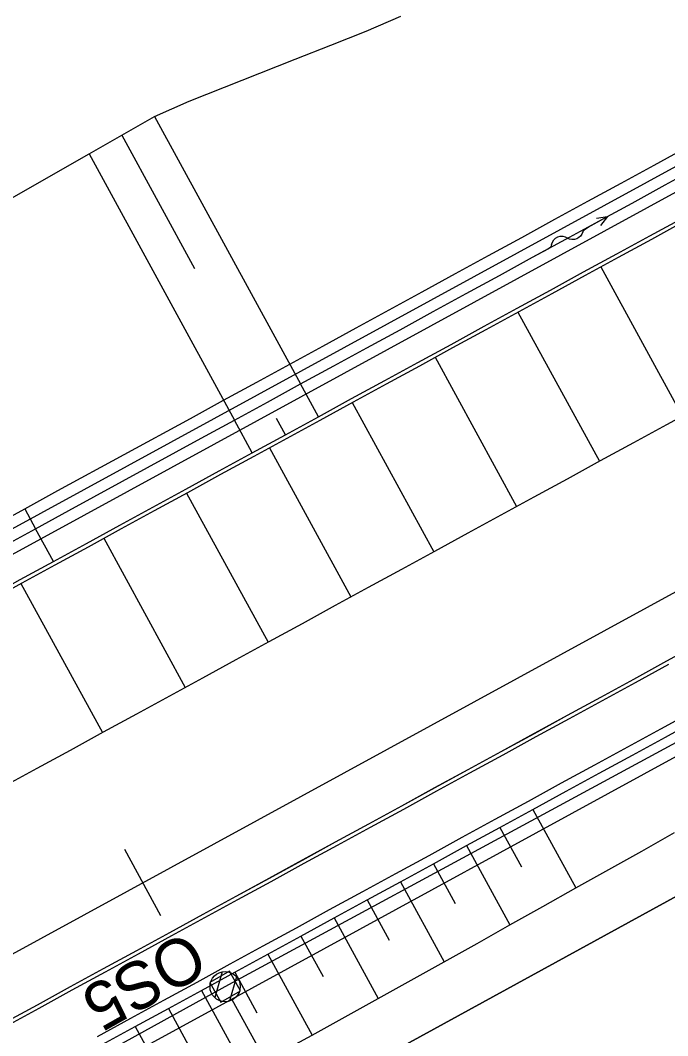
# Model space of a CAD drawing. Extents: x -783978 to -783565, y -1064821 to -1064596.
# Drawn here: x -783827.85 to -783810.7, y -1064718.73 to -1064691.83 of the extents above; entities that cross this region are included whole.
import ezdxf

# ---------------------------------------------------------------- set-up
doc = ezdxf.new("R2010")
doc.units = 0
for name, color, linetype in [('PS 01_01_10', 7, 'Continuous'), ('PS 01_02_501', 7, 'Continuous'), ('PS 01_02_502', 7, 'Continuous'), ('SO 01_50_01', 7, 'Continuous'), ('SO 01_79_02', 7, 'Continuous'), ('SO 01_86_02', 7, 'Continuous'), ('SO 01_86_03', 7, 'Continuous')]:
    doc.layers.add(name, color=color, linetype=linetype)

# ---------------------------------------------------------------- blocks, each defined once
blk = doc.blocks.new('SIPKP')
at = {"layer": 'SO 01_50_01'}
for p, q in [((0, 0), (19.5, 0)), ((67.1, 0.2), (74.2, 0.2)), ((74.2, 0.2), (90.5, 0.2)), ((90.5, 0.2), (79.4, 4.9)), ((79.4, -4.1), (90.5, 0.2))]:
    blk.add_line(p, q, dxfattribs=at)
for centre, radius, start, end in [((19.6, -5.8), 5.82, 37.3192, 90.4169), ((51.6, -5.8), 11.1, 42.7386, 149.222), ((66.6, 17.1), 16.9, 245.3105, 271.7078), ((32.5, 4.2), 10.5, 218.0257, 335.7054)]:
    blk.add_arc(centre, radius, start, end, dxfattribs=at)

msp = doc.modelspace()

# ---------------------------------------------------------------- linework, layer by layer
at = {"layer": 'PS 01_01_10'}
msp.add_lwpolyline([(-783718.942, -1064658.936), (-783725.964, -1064662.689), (-783732.354, -1064665.912), (-783735.21, -1064660.697), (-783789.362, -1064690.348), (-783783.825, -1064700.441), (-783871.436, -1064748.425), (-783875.857, -1064749.835)], dxfattribs=at)
at = {"layer": 'PS 01_02_501'}
msp.add_lwpolyline([(-783952.311, -1064789.972), (-783925.027, -1064771.233), (-783922.857, -1064767.935), (-783921.132, -1064767.225), (-783922.344, -1064769.056), (-783920.816, -1064771.043), (-783917.67, -1064770.417), (-783911.05, -1064766.471), (-783887.429, -1064753.525), (-783871.436, -1064748.425), (-783783.828, -1064700.439), (-783789.362, -1064690.348), (-783735.226, -1064660.707), (-783727.19, -1064659.072), (-783724.297, -1064658.484), (-783715.521, -1064653.988), (-783697.391, -1064644.148), (-783676.268, -1064633.506), (-783655.138, -1064621.894)], dxfattribs=at)
at = {"layer": 'PS 01_02_502'}
msp.add_lwpolyline([(-783952.311, -1064789.972), (-783925.027, -1064771.233), (-783922.857, -1064767.935), (-783921.132, -1064767.225), (-783922.344, -1064769.056), (-783920.816, -1064771.043), (-783917.67, -1064770.417), (-783911.05, -1064766.471), (-783887.429, -1064753.525), (-783871.436, -1064748.425), (-783783.828, -1064700.439), (-783789.362, -1064690.348), (-783735.226, -1064660.707), (-783727.19, -1064659.072), (-783724.297, -1064658.484), (-783715.521, -1064653.988), (-783697.391, -1064644.148), (-783676.268, -1064633.506), (-783655.138, -1064621.894)], dxfattribs=at)
at = {"layer": 'SO 01_50_01'}
for p, q in [((-783868.841, -1064727.56), (-783794.223, -1064686.815)), ((-783868.554, -1064728.087), (-783793.967, -1064687.359)), ((-783818.692, -1064692.119), (-783817.768, -1064691.724)), ((-783819.629, -1064692.489), (-783818.692, -1064692.119)), ((-783820.566, -1064692.86), (-783819.629, -1064692.489)), ((-783821.503, -1064693.231), (-783820.566, -1064692.86)), ((-783822.44, -1064693.601), (-783821.503, -1064693.231)), ((-783867.163, -1064737.91), (-783786.213, -1064693.707)), ((-783823.377, -1064693.972), (-783822.44, -1064693.601)), ((-783824.295, -1064694.378), (-783823.377, -1064693.972)), ((-783825.162, -1064694.876), (-783824.295, -1064694.378)), ((-783824.295, -1064694.378), (-783820.425, -1064701.464)), ((-783826.03, -1064695.373), (-783825.162, -1064694.876)), ((-783825.162, -1064694.876), (-783823.233, -1064698.41)), ((-783811.058, -1064695.666), (-783810.181, -1064695.187)), ((-783849.497, -1064708.734), (-783826.03, -1064695.373)), ((-783826.03, -1064695.373), (-783822.181, -1064702.423)), ((-783811.936, -1064696.145), (-783811.058, -1064695.666)), ((-783810.771, -1064696.193), (-783809.893, -1064695.713)), ((-783812.814, -1064696.625), (-783811.936, -1064696.145)), ((-783811.648, -1064696.672), (-783810.771, -1064696.193)), ((-783813.691, -1064697.104), (-783812.814, -1064696.625)), ((-783812.526, -1064697.151), (-783811.648, -1064696.672)), ((-783811.175, -1064697.539), (-783810.297, -1064697.06)), ((-783811.175, -1064697.539), (-783810.297, -1064697.06)), ((-783811.175, -1064697.539), (-783810.297, -1064697.06)), ((-783814.569, -1064697.583), (-783813.691, -1064697.104)), ((-783813.404, -1064697.63), (-783812.526, -1064697.151)), ((-783811.127, -1064697.627), (-783810.249, -1064697.148)), ((-783815.447, -1064698.062), (-783814.569, -1064697.583)), ((-783814.281, -1064698.11), (-783813.404, -1064697.63)), ((-783812.053, -1064698.018), (-783811.175, -1064697.539)), ((-783812.053, -1064698.018), (-783811.175, -1064697.539)), ((-783812.053, -1064698.018), (-783811.175, -1064697.539)), ((-783812.005, -1064698.106), (-783811.127, -1064697.627)), ((-783816.324, -1064698.542), (-783815.447, -1064698.062)), ((-783815.159, -1064698.589), (-783814.281, -1064698.11)), ((-783812.93, -1064698.498), (-783812.053, -1064698.018)), ((-783812.93, -1064698.498), (-783812.053, -1064698.018)), ((-783812.93, -1064698.498), (-783812.053, -1064698.018)), ((-783812.882, -1064698.585), (-783812.005, -1064698.106)), ((-783817.202, -1064699.021), (-783816.324, -1064698.542)), ((-783816.037, -1064699.068), (-783815.159, -1064698.589)), ((-783813.808, -1064698.977), (-783812.93, -1064698.498)), ((-783813.808, -1064698.977), (-783812.93, -1064698.498)), ((-783813.808, -1064698.977), (-783812.93, -1064698.498)), ((-783813.76, -1064699.065), (-783812.882, -1064698.585)), ((-783814.686, -1064699.456), (-783813.808, -1064698.977)), ((-783814.686, -1064699.456), (-783813.808, -1064698.977)), ((-783814.686, -1064699.456), (-783813.808, -1064698.977)), ((-783818.08, -1064699.5), (-783817.202, -1064699.021)), ((-783816.914, -1064699.547), (-783816.037, -1064699.068)), ((-783814.638, -1064699.544), (-783813.76, -1064699.065)), ((-783818.957, -1064699.979), (-783818.08, -1064699.5)), ((-783815.563, -1064699.935), (-783814.686, -1064699.456)), ((-783815.563, -1064699.935), (-783814.686, -1064699.456)), ((-783815.563, -1064699.935), (-783814.686, -1064699.456)), ((-783817.792, -1064700.027), (-783816.914, -1064699.547)), ((-783815.515, -1064700.023), (-783814.638, -1064699.544)), ((-783819.835, -1064700.459), (-783818.957, -1064699.979)), ((-783818.67, -1064700.506), (-783817.792, -1064700.027)), ((-783816.441, -1064700.415), (-783815.563, -1064699.935)), ((-783816.441, -1064700.415), (-783815.563, -1064699.935)), ((-783816.441, -1064700.415), (-783815.563, -1064699.935)), ((-783816.393, -1064700.502), (-783815.515, -1064700.023)), ((-783820.713, -1064700.938), (-783819.835, -1064700.459)), ((-783819.548, -1064700.985), (-783818.67, -1064700.506)), ((-783817.319, -1064700.894), (-783816.441, -1064700.415)), ((-783817.319, -1064700.894), (-783816.441, -1064700.415)), ((-783817.319, -1064700.894), (-783816.441, -1064700.415)), ((-783817.271, -1064700.982), (-783816.393, -1064700.502)), ((-783821.59, -1064701.417), (-783820.713, -1064700.938)), ((-783820.425, -1064701.464), (-783819.548, -1064700.985)), ((-783818.196, -1064701.373), (-783817.319, -1064700.894)), ((-783818.196, -1064701.373), (-783817.319, -1064700.894)), ((-783818.196, -1064701.373), (-783817.319, -1064700.894)), ((-783818.148, -1064701.461), (-783817.271, -1064700.982)), ((-783819.074, -1064701.852), (-783818.196, -1064701.373)), ((-783819.074, -1064701.852), (-783818.196, -1064701.373)), ((-783819.074, -1064701.852), (-783818.196, -1064701.373)), ((-783822.468, -1064701.896), (-783821.59, -1064701.417)), ((-783821.303, -1064701.944), (-783820.425, -1064701.464)), ((-783819.952, -1064702.332), (-783820.425, -1064701.464)), ((-783819.026, -1064701.94), (-783818.148, -1064701.461)), ((-783823.346, -1064702.376), (-783822.468, -1064701.896)), ((-783819.952, -1064702.332), (-783819.074, -1064701.852)), ((-783819.952, -1064702.332), (-783819.074, -1064701.852)), ((-783819.952, -1064702.332), (-783819.074, -1064701.852)), ((-783822.181, -1064702.423), (-783821.303, -1064701.944)), ((-783819.904, -1064702.419), (-783819.026, -1064701.94)), ((-783810.726, -1064702.535), (-783809.848, -1064702.056)), ((-783826.858, -1064704.29), (-783823.346, -1064702.376)), ((-783823.058, -1064702.902), (-783822.181, -1064702.423)), ((-783821.707, -1064703.29), (-783822.181, -1064702.423)), ((-783820.829, -1064702.811), (-783821.066, -1064702.377)), ((-783820.829, -1064702.811), (-783819.952, -1064702.332)), ((-783820.829, -1064702.811), (-783819.952, -1064702.332)), ((-783820.829, -1064702.811), (-783819.952, -1064702.332)), ((-783820.781, -1064702.899), (-783819.904, -1064702.419)), ((-783811.603, -1064703.014), (-783810.726, -1064702.535)), ((-783826.569, -1064704.819), (-783823.058, -1064702.902)), ((-783821.707, -1064703.29), (-783820.829, -1064702.811)), ((-783821.707, -1064703.29), (-783820.829, -1064702.811)), ((-783821.707, -1064703.29), (-783820.829, -1064702.811)), ((-783821.659, -1064703.378), (-783820.781, -1064702.899)), ((-783812.481, -1064703.493), (-783811.603, -1064703.014)), ((-783822.585, -1064703.769), (-783821.707, -1064703.29)), ((-783822.585, -1064703.769), (-783821.707, -1064703.29)), ((-783822.585, -1064703.769), (-783821.707, -1064703.29)), ((-783822.537, -1064703.857), (-783821.659, -1064703.378)), ((-783813.359, -1064703.973), (-783812.481, -1064703.493)), ((-783823.462, -1064704.249), (-783822.585, -1064703.769)), ((-783823.462, -1064704.249), (-783822.585, -1064703.769)), ((-783823.462, -1064704.249), (-783822.585, -1064703.769)), ((-783823.414, -1064704.336), (-783822.537, -1064703.857)), ((-783814.236, -1064704.452), (-783813.359, -1064703.973)), ((-783827.735, -1064704.772), (-783826.858, -1064704.29)), ((-783824.34, -1064704.728), (-783823.462, -1064704.249)), ((-783824.34, -1064704.728), (-783823.462, -1064704.249)), ((-783824.34, -1064704.728), (-783823.462, -1064704.249)), ((-783824.292, -1064704.816), (-783823.414, -1064704.336)), ((-783815.114, -1064704.931), (-783814.236, -1064704.452)), ((-783828.612, -1064705.251), (-783827.734, -1064704.772)), ((-783827.735, -1064704.772), (-783827.447, -1064705.298)), ((-783827.447, -1064705.298), (-783826.569, -1064704.819)), ((-783825.218, -1064705.207), (-783824.34, -1064704.728)), ((-783825.218, -1064705.207), (-783824.34, -1064704.728)), ((-783825.218, -1064705.207), (-783824.34, -1064704.728)), ((-783825.17, -1064705.295), (-783824.292, -1064704.816)), ((-783815.992, -1064705.41), (-783815.114, -1064704.931)), ((-783828.324, -1064705.778), (-783827.447, -1064705.298)), ((-783826.973, -1064706.166), (-783827.447, -1064705.298)), ((-783826.095, -1064705.686), (-783825.218, -1064705.207)), ((-783826.095, -1064705.686), (-783825.218, -1064705.207)), ((-783826.095, -1064705.686), (-783825.218, -1064705.207)), ((-783826.047, -1064705.774), (-783825.17, -1064705.295)), ((-783816.869, -1064705.89), (-783815.992, -1064705.41)), ((-783826.973, -1064706.166), (-783826.095, -1064705.686)), ((-783826.973, -1064706.166), (-783826.095, -1064705.686)), ((-783826.973, -1064706.166), (-783826.095, -1064705.686)), ((-783826.925, -1064706.253), (-783826.047, -1064705.774)), ((-783817.747, -1064706.369), (-783816.869, -1064705.89)), ((-783827.851, -1064706.645), (-783826.973, -1064706.166)), ((-783827.851, -1064706.645), (-783826.973, -1064706.166)), ((-783827.851, -1064706.645), (-783826.973, -1064706.166)), ((-783827.803, -1064706.733), (-783826.925, -1064706.253)), ((-783818.625, -1064706.848), (-783817.747, -1064706.369)), ((-783828.728, -1064707.124), (-783827.851, -1064706.645)), ((-783828.728, -1064707.124), (-783827.851, -1064706.645)), ((-783828.728, -1064707.124), (-783827.851, -1064706.645)), ((-783828.68, -1064707.212), (-783827.803, -1064706.733)), ((-783819.502, -1064707.327), (-783818.625, -1064706.848)), ((-783820.38, -1064707.807), (-783819.502, -1064707.327)), ((-783821.258, -1064708.286), (-783820.38, -1064707.807)), ((-783822.135, -1064708.765), (-783821.258, -1064708.286)), ((-783810.723, -1064708.8), (-783809.845, -1064708.321)), ((-783810.722, -1064708.801), (-783809.845, -1064708.321)), ((-783823.013, -1064709.244), (-783822.135, -1064708.765)), ((-783811.6, -1064709.279), (-783810.723, -1064708.8)), ((-783811.6, -1064709.28), (-783810.722, -1064708.801)), ((-783811.553, -1064709.367), (-783810.675, -1064708.888)), ((-783823.891, -1064709.724), (-783823.013, -1064709.244)), ((-783812.478, -1064709.758), (-783811.6, -1064709.279)), ((-783812.478, -1064709.759), (-783811.6, -1064709.28)), ((-783812.43, -1064709.846), (-783811.553, -1064709.367)), ((-783824.768, -1064710.203), (-783823.891, -1064709.724)), ((-783813.356, -1064710.238), (-783812.478, -1064709.758)), ((-783813.355, -1064710.238), (-783812.478, -1064709.759)), ((-783813.308, -1064710.325), (-783812.43, -1064709.846)), ((-783825.646, -1064710.682), (-783824.768, -1064710.203)), ((-783814.233, -1064710.718), (-783813.355, -1064710.238)), ((-783814.233, -1064710.717), (-783813.356, -1064710.238)), ((-783810.882, -1064710.596), (-783810.004, -1064710.116)), ((-783814.186, -1064710.805), (-783813.308, -1064710.325)), ((-783810.762, -1064710.815), (-783809.884, -1064710.336)), ((-783810.762, -1064710.815), (-783809.884, -1064710.336)), ((-783810.762, -1064710.815), (-783809.884, -1064710.336)), ((-783826.524, -1064711.161), (-783825.646, -1064710.682)), ((-783815.111, -1064711.196), (-783814.233, -1064710.717)), ((-783815.111, -1064711.197), (-783814.233, -1064710.718)), ((-783815.063, -1064711.284), (-783814.186, -1064710.805)), ((-783811.759, -1064711.075), (-783810.882, -1064710.596)), ((-783812.637, -1064711.554), (-783811.759, -1064711.075)), ((-783811.639, -1064711.294), (-783810.762, -1064710.815)), ((-783811.639, -1064711.294), (-783810.762, -1064710.815)), ((-783811.639, -1064711.294), (-783810.762, -1064710.815)), ((-783827.402, -1064711.641), (-783826.524, -1064711.161)), ((-783815.989, -1064711.675), (-783815.111, -1064711.196)), ((-783815.988, -1064711.676), (-783815.111, -1064711.197)), ((-783815.941, -1064711.763), (-783815.063, -1064711.284)), ((-783812.517, -1064711.774), (-783811.639, -1064711.294)), ((-783812.517, -1064711.774), (-783811.639, -1064711.294)), ((-783812.517, -1064711.774), (-783811.639, -1064711.294)), ((-783813.515, -1064712.033), (-783812.637, -1064711.554)), ((-783828.279, -1064712.12), (-783827.402, -1064711.641)), ((-783816.867, -1064712.155), (-783815.989, -1064711.675)), ((-783816.866, -1064712.155), (-783815.988, -1064711.676)), ((-783816.819, -1064712.242), (-783815.941, -1064711.763)), ((-783813.395, -1064712.253), (-783812.517, -1064711.774)), ((-783813.395, -1064712.253), (-783812.517, -1064711.774)), ((-783813.395, -1064712.253), (-783812.517, -1064711.774)), ((-783817.744, -1064712.635), (-783816.866, -1064712.155)), ((-783817.744, -1064712.634), (-783816.867, -1064712.155)), ((-783814.392, -1064712.513), (-783813.515, -1064712.033)), ((-783817.696, -1064712.722), (-783816.819, -1064712.242)), ((-783814.272, -1064712.732), (-783813.395, -1064712.253)), ((-783814.272, -1064712.732), (-783813.395, -1064712.253)), ((-783814.272, -1064712.732), (-783813.395, -1064712.253)), ((-783818.622, -1064713.113), (-783817.744, -1064712.634)), ((-783818.621, -1064713.114), (-783817.744, -1064712.635)), ((-783815.27, -1064712.992), (-783814.392, -1064712.513)), ((-783818.574, -1064713.201), (-783817.696, -1064712.722)), ((-783815.15, -1064713.211), (-783814.272, -1064712.732)), ((-783815.15, -1064713.211), (-783814.272, -1064712.732)), ((-783815.15, -1064713.211), (-783814.272, -1064712.732)), ((-783814.272, -1064712.732), (-783813.136, -1064714.814)), ((-783819.5, -1064713.592), (-783818.622, -1064713.113)), ((-783819.499, -1064713.593), (-783818.621, -1064713.114)), ((-783819.452, -1064713.68), (-783818.574, -1064713.201)), ((-783816.148, -1064713.471), (-783815.27, -1064712.992)), ((-783816.028, -1064713.691), (-783815.15, -1064713.211)), ((-783816.028, -1064713.691), (-783815.15, -1064713.211)), ((-783816.028, -1064713.691), (-783815.15, -1064713.211)), ((-783815.15, -1064713.211), (-783814.579, -1064714.257)), ((-783817.025, -1064713.95), (-783816.148, -1064713.471)), ((-783811.391, -1064713.836), (-783810.519, -1064713.347)), ((-783820.377, -1064714.072), (-783819.5, -1064713.592)), ((-783820.377, -1064714.073), (-783819.499, -1064713.593)), ((-783820.329, -1064714.159), (-783819.452, -1064713.68)), ((-783816.905, -1064714.17), (-783816.028, -1064713.691)), ((-783816.905, -1064714.17), (-783816.028, -1064713.691)), ((-783816.905, -1064714.17), (-783816.028, -1064713.691)), ((-783816.028, -1064713.691), (-783814.88, -1064715.793)), ((-783824.128, -1064715.55), (-783825.086, -1064713.794)), ((-783817.903, -1064714.43), (-783817.025, -1064713.95)), ((-783812.263, -1064714.325), (-783811.391, -1064713.836)), ((-783821.255, -1064714.551), (-783820.377, -1064714.072)), ((-783821.254, -1064714.552), (-783820.377, -1064714.073)), ((-783821.207, -1064714.639), (-783820.329, -1064714.159)), ((-783817.783, -1064714.649), (-783816.905, -1064714.17)), ((-783817.783, -1064714.649), (-783816.905, -1064714.17)), ((-783817.783, -1064714.649), (-783816.905, -1064714.17)), ((-783816.905, -1064714.17), (-783816.329, -1064715.226)), ((-783822.133, -1064715.03), (-783821.255, -1064714.551)), ((-783822.132, -1064715.031), (-783821.254, -1064714.552)), ((-783818.781, -1064714.909), (-783817.903, -1064714.43)), ((-783813.136, -1064714.814), (-783812.263, -1064714.325)), ((-783822.085, -1064715.118), (-783821.207, -1064714.639)), ((-783818.661, -1064715.128), (-783817.783, -1064714.649)), ((-783818.661, -1064715.128), (-783817.783, -1064714.649)), ((-783818.661, -1064715.128), (-783817.783, -1064714.649)), ((-783817.783, -1064714.649), (-783816.624, -1064716.771)), ((-783814.008, -1064715.303), (-783813.136, -1064714.814)), ((-783823.01, -1064715.509), (-783822.133, -1064715.03)), ((-783823.01, -1064715.51), (-783822.132, -1064715.031)), ((-783819.658, -1064715.388), (-783818.781, -1064714.909)), ((-783822.962, -1064715.597), (-783822.085, -1064715.118)), ((-783819.539, -1064715.608), (-783818.661, -1064715.128)), ((-783819.539, -1064715.608), (-783818.661, -1064715.128)), ((-783819.539, -1064715.608), (-783818.661, -1064715.128)), ((-783818.661, -1064715.128), (-783818.079, -1064716.193)), ((-783814.88, -1064715.793), (-783814.008, -1064715.303)), ((-783823.888, -1064715.989), (-783823.01, -1064715.509)), ((-783823.887, -1064715.99), (-783823.01, -1064715.51)), ((-783823.84, -1064716.076), (-783822.962, -1064715.597)), ((-783820.536, -1064715.867), (-783819.658, -1064715.388)), ((-783820.416, -1064716.087), (-783819.539, -1064715.608)), ((-783820.416, -1064716.087), (-783819.539, -1064715.608)), ((-783820.416, -1064716.087), (-783819.539, -1064715.608)), ((-783819.539, -1064715.608), (-783818.373, -1064717.742)), ((-783821.414, -1064716.347), (-783820.536, -1064715.867)), ((-783815.752, -1064716.282), (-783814.88, -1064715.793)), ((-783824.766, -1064716.468), (-783823.888, -1064715.989)), ((-783824.765, -1064716.469), (-783823.887, -1064715.99)), ((-783824.718, -1064716.556), (-783823.84, -1064716.076)), ((-783821.294, -1064716.566), (-783820.416, -1064716.087)), ((-783821.294, -1064716.566), (-783820.416, -1064716.087)), ((-783821.294, -1064716.566), (-783820.416, -1064716.087)), ((-783820.416, -1064716.087), (-783819.832, -1064717.156)), ((-783822.291, -1064716.826), (-783821.414, -1064716.347)), ((-783816.624, -1064716.771), (-783815.752, -1064716.282)), ((-783825.643, -1064716.947), (-783824.766, -1064716.468)), ((-783825.643, -1064716.948), (-783824.765, -1064716.469)), ((-783825.595, -1064717.035), (-783824.718, -1064716.556)), ((-783822.172, -1064717.045), (-783821.294, -1064716.566)), ((-783822.172, -1064717.045), (-783821.294, -1064716.566)), ((-783822.172, -1064717.045), (-783821.294, -1064716.566)), ((-783821.294, -1064716.566), (-783820.124, -1064718.709)), ((-783826.521, -1064717.426), (-783825.643, -1064716.947)), ((-783826.52, -1064717.427), (-783825.643, -1064716.948)), ((-783823.169, -1064717.305), (-783822.291, -1064716.826)), ((-783817.498, -1064717.258), (-783816.624, -1064716.771)), ((-783826.473, -1064717.514), (-783825.595, -1064717.035)), ((-783823.049, -1064717.525), (-783822.172, -1064717.045)), ((-783823.049, -1064717.525), (-783822.172, -1064717.045)), ((-783823.049, -1064717.525), (-783822.172, -1064717.045)), ((-783822.172, -1064717.045), (-783821.586, -1064718.119)), ((-783818.373, -1064717.742), (-783817.498, -1064717.258)), ((-783827.399, -1064717.906), (-783826.521, -1064717.426)), ((-783827.398, -1064717.907), (-783826.52, -1064717.427)), ((-783827.351, -1064717.993), (-783826.473, -1064717.514)), ((-783824.047, -1064717.784), (-783823.169, -1064717.305)), ((-783823.927, -1064718.004), (-783823.049, -1064717.525)), ((-783823.927, -1064718.004), (-783823.049, -1064717.525)), ((-783823.927, -1064718.004), (-783823.049, -1064717.525)), ((-783823.049, -1064717.525), (-783821.874, -1064719.676)), ((-783824.924, -1064718.264), (-783824.047, -1064717.784)), ((-783819.248, -1064718.225), (-783818.373, -1064717.742)), ((-783828.276, -1064718.385), (-783827.399, -1064717.906)), ((-783828.276, -1064718.386), (-783827.398, -1064717.907)), ((-783828.228, -1064718.473), (-783827.351, -1064717.993)), ((-783824.805, -1064718.483), (-783823.927, -1064718.004)), ((-783824.805, -1064718.483), (-783823.927, -1064718.004)), ((-783824.805, -1064718.483), (-783823.927, -1064718.004)), ((-783823.927, -1064718.004), (-783823.339, -1064719.082)), ((-783825.802, -1064718.743), (-783824.924, -1064718.264)), ((-783820.124, -1064718.709), (-783819.248, -1064718.225)), ((-783825.682, -1064718.962), (-783824.805, -1064718.483)), ((-783825.682, -1064718.962), (-783824.805, -1064718.483)), ((-783825.682, -1064718.962), (-783824.805, -1064718.483)), ((-783824.805, -1064718.483), (-783823.625, -1064720.643)), ((-783820.999, -1064719.193), (-783820.124, -1064718.709))]:
    msp.add_line(p, q, dxfattribs=at)
for points in [[(-783812.475, -1064698.363), (-783810.318, -1064702.312)], [(-783814.669, -1064699.561), (-783812.512, -1064703.511)], [(-783816.863, -1064700.759), (-783814.707, -1064704.709)], [(-783819.058, -1064701.957), (-783816.901, -1064705.907)], [(-783821.252, -1064703.155), (-783819.095, -1064707.105)], [(-783823.446, -1064704.353), (-783821.289, -1064708.303)], [(-783825.64, -1064705.552), (-783823.483, -1064709.501)], [(-783827.834, -1064706.75), (-783825.678, -1064710.699)]]:
    msp.add_lwpolyline(points, dxfattribs=at)
at = {"layer": 'SO 01_79_02'}
msp.add_lwpolyline([(-783745.082, -1064674.977), (-783746.507, -1064675.757), (-783748.147, -1064676.664), (-783749.691, -1064678.136), (-783784.257, -1064697.013), (-783798.19, -1064704.62), (-783800.06, -1064705.37), (-783802.52, -1064706.72), (-783803.71, -1064707.63), (-783853.11, -1064734.61), (-783855.1, -1064735.3), (-783857.05, -1064736.37), (-783858.65, -1064737.64), (-783871.68, -1064744.75), (-783877.056, -1064744.607), (-783887.429, -1064744.062), (-783898.089, -1064743.49), (-783899.421, -1064743.418)], dxfattribs=at)
at = {"layer": 'SO 01_86_02'}
for p, q in [((-783822.501, -1064717.038), (-783822.7, -1064717.717)), ((-783822.123, -1064717.17), (-783822.31, -1064717.807)), ((-783821.516, -1064719.095), (-783822.235, -1064717.778))]:
    msp.add_line(p, q, dxfattribs=at)
msp.add_lwpolyline([(-783878.186, -1064744.275), (-783875.129, -1064744.345), (-783874.695, -1064744.328), (-783873.251, -1064744.157), (-783872.314, -1064743.982), (-783871.219, -1064743.702), (-783870.515, -1064743.486), (-783869.798, -1064743.212), (-783869.177, -1064742.975), (-783868.711, -1064742.765), (-783868.395, -1064742.607), (-783868.078, -1064742.449), (-783860.975, -1064738.569), (-783850.672, -1064732.611), (-783846.246, -1064730.189), (-783839.947, -1064727.086), (-783822.426, -1064717.427), (-783813.356, -1064712.518), (-783804.285, -1064707.61), (-783794.474, -1064702.252), (-783784.661, -1064696.896), (-783775.734, -1064692.013), (-783766.806, -1064687.131), (-783750.626, -1064678.282)], dxfattribs=at)
msp.add_lwpolyline([(-783822.54, -1064717.836), (-783822.018, -1064717.541), (-783822.313, -1064717.018), (-783822.835, -1064717.313)], close=True, dxfattribs=at)
msp.add_circle((-783822.426, -1064717.427), 0.4, dxfattribs=at)
at = {"layer": 'SO 01_86_03'}
msp.add_lwpolyline([(-783722.521, -1064661.793), (-783724.821, -1064663.049), (-783735.21, -1064660.697), (-783787.333, -1064689.237), (-783786.817, -1064690.18), (-783783.359, -1064696.803), (-783781.939, -1064699.409), (-783783.828, -1064700.439), (-783871.436, -1064748.425), (-783875.857, -1064749.835), (-783877.538, -1064747.393), (-783875.857, -1064749.835), (-783887.429, -1064753.525), (-783911.05, -1064766.471), (-783917.67, -1064770.417), (-783920.816, -1064771.043), (-783922.344, -1064769.056), (-783922.498, -1064767.051)], dxfattribs=at)

# ---------------------------------------------------------------- block references
at = {"layer": 'SO 01_50_01', "xscale": 0.02497499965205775, "yscale": -0.02497499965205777, "rotation": 28.63656000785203}
msp.add_blockref('SIPKP', (-783814.281, -1064698.11), dxfattribs=at)

# ---------------------------------------------------------------- texts
at = {"layer": 'SO 01_86_02'}
msp.add_text('OS5', height=1.25, rotation=209.446, dxfattribs=at).set_placement((-783823.413, -1064715.924))

doc.saveas('drawing.dxf')
